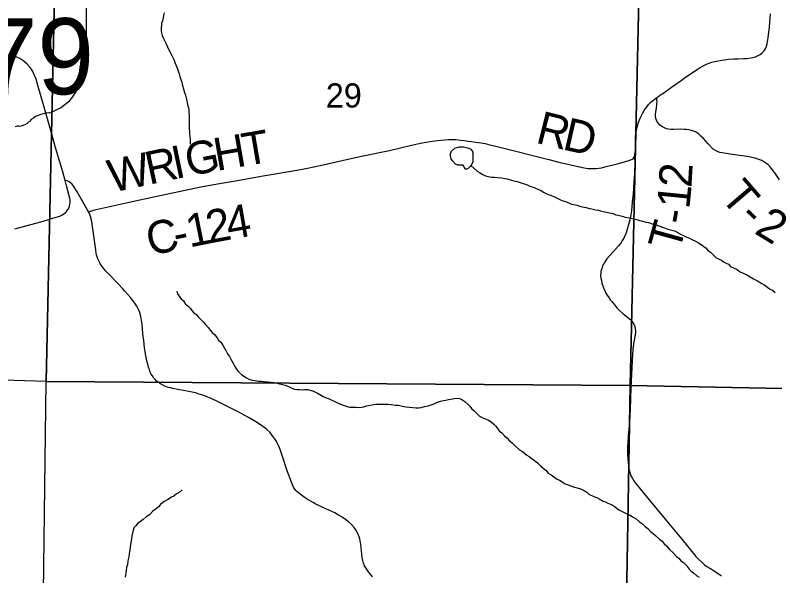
# Model space of a CAD drawing. Extents: x 0 to 34, y 0 to 22.
# Drawn here: x 27.832 to 29.148, y 18.224 to 19.195 of the extents above; entities that cross this region are included whole.
import ezdxf

# ---------------------------------------------------------------- set-up
doc = ezdxf.new("R2010")
doc.units = 0
for name, color, linetype in [('GM_X_Corporation', 7, 'Continuous'), ('GM_X_County_Road', 7, 'Continuous'), ('GM_X_County_Road_Text', 7, 'Continuous'), ('GM_X_Minor_River', 7, 'Continuous'), ('GM_X_Section_Text', 7, 'Continuous'), ('GM_X_State_Route', 7, 'Continuous'), ('GM_X_State_Shield', 7, 'Continuous'), ('GM_X_Township_Road', 7, 'Continuous'), ('GM_X_Township_Road_Text', 7, 'Continuous')]:
    doc.layers.add(name, color=color, linetype=linetype)

msp = doc.modelspace()

# ---------------------------------------------------------------- linework, layer by layer
at = {"layer": 'GM_X_Corporation'}
for points in [[(27.9077, 19.5783), (27.8861, 18.5601), (27.0567, 18.5863), (27.0782, 19.5962)], [(27.9077, 19.5783), (28.9198, 19.5578), (28.8973, 18.5532), (27.8861, 18.5601)], [(28.9198, 19.5578), (29.946, 19.5413), (29.9261, 18.5329), (28.8973, 18.5532)], [(28.8973, 18.5532), (28.8799, 17.5369), (27.873, 17.5549), (27.8861, 18.5601)], [(29.9261, 18.5329), (29.9011, 17.5188), (28.8799, 17.5369), (28.8973, 18.5532)]]:
    msp.add_lwpolyline(points, close=True, dxfattribs=at)
at = {"layer": 'GM_X_County_Road'}
for points in [[(27.9596, 18.8542), (27.9684, 18.8574), (27.9724, 18.8585), (28.0245, 18.8697), (28.0484, 18.875), (28.0779, 18.8812), (28.1351, 18.8938), (28.1541, 18.8976), (28.1862, 18.9034), (28.2137, 18.9082), (28.2618, 18.9166), (28.3063, 18.9241), (28.3235, 18.9271), (28.3384, 18.9301), (28.3494, 18.9324), (28.3603, 18.9348), (28.3858, 18.9406), (28.4292, 18.9501), (28.4807, 18.9609), (28.5185, 18.9696), (28.5342, 18.9732), (28.544, 18.9751), (28.5548, 18.9768), (28.56, 18.9774), (28.5698, 18.9786), (28.576, 18.9792), (28.5827, 18.9795), (28.5959, 18.9794), (28.6038, 18.9788), (28.6096, 18.9782), (28.6304, 18.9753), (28.6397, 18.9737), (28.6462, 18.9725), (28.6543, 18.9707), (28.6674, 18.9677), (28.6992, 18.9596), (28.7288, 18.9521), (28.7564, 18.9451), (28.7763, 18.9401), (28.7898, 18.9369), (28.8152, 18.931), (28.8211, 18.93), (28.825, 18.9295), (28.8282, 18.9293), (28.8312, 18.9292), (28.8387, 18.9294), (28.8434, 18.9299), (28.8476, 18.9307), (28.8561, 18.9327), (28.8732, 18.9369), (28.8814, 18.9391), (28.8957, 18.9434), (28.8997, 18.945), (28.9013, 18.9458), (28.9026, 18.9468), (28.9034, 18.9478), (28.9041, 18.949), (28.9047, 18.9504), (28.9053, 18.9523), (28.9058, 18.9544), (28.9062, 18.9573), (28.9065, 18.961), (28.9066, 18.9767), (28.907, 18.9847), (28.9074, 18.9889), (28.9084, 18.9956), (28.9095, 19.001), (28.9105, 19.0049), (28.9114, 19.008), (28.9137, 19.0137), (28.9161, 19.0189), (28.9196, 19.0256), (28.922, 19.0297), (28.9257, 19.0355), (28.9282, 19.0387), (28.9295, 19.0404), (28.9312, 19.0421), (28.933, 19.044), (28.9361, 19.0468), (28.9389, 19.0489), (28.9434, 19.0522), (28.9471, 19.0548), (28.9502, 19.0569), (28.9533, 19.0591), (28.9688, 19.0701), (28.9856, 19.082), (28.9936, 19.0877), (29.0138, 19.1012), (29.0186, 19.1043), (29.0228, 19.1067), (29.0286, 19.1096), (29.0325, 19.1114), (29.0388, 19.1136), (29.044, 19.115), (29.0561, 19.1172), (29.0611, 19.118), (29.0679, 19.1187), (29.0762, 19.1193), (29.0842, 19.1195), (29.0939, 19.1198), (29.1003, 19.1202), (29.1063, 19.121), (29.1104, 19.1219), (29.1148, 19.1232), (29.1193, 19.125), (29.1225, 19.1267), (29.1263, 19.1299), (29.129, 19.1328), (29.1308, 19.1353), (29.1322, 19.138), (29.1336, 19.1417), (29.1347, 19.1454), (29.1368, 19.1559), (29.1391, 19.1751), (29.1408, 19.1975)], [(27.9596, 18.8542), (27.9397, 18.8888), (27.9345, 18.8971), (27.9325, 18.9002), (27.9304, 18.9029), (27.9284, 18.9048), (27.9258, 18.9065), (27.9225, 18.9078), (27.9191, 18.9084)], [(28.4513, 18.222), (28.4445, 18.2303), (28.4418, 18.2339), (28.4396, 18.2372), (28.4376, 18.2407), (28.4357, 18.2454), (28.4342, 18.2503), (28.4332, 18.2553), (28.4322, 18.2668), (28.4317, 18.2727), (28.431, 18.2784), (28.4299, 18.2842), (28.429, 18.2877), (28.4276, 18.2927), (28.4266, 18.2954), (28.4255, 18.2978), (28.4234, 18.3017), (28.4222, 18.3035), (28.4195, 18.3073), (28.4146, 18.3128), (28.4095, 18.3171), (28.4043, 18.3212), (28.3984, 18.3252), (28.3926, 18.3289), (28.3857, 18.3326), (28.3706, 18.3399), (28.352, 18.3485), (28.3495, 18.3498), (28.347, 18.3512), (28.3397, 18.3554), (28.3328, 18.3599), (28.326, 18.3648), (28.3201, 18.3697), (28.3184, 18.3715), (28.3168, 18.3736), (28.3157, 18.3752), (28.3146, 18.3772), (28.3126, 18.3813), (28.3109, 18.3859), (28.3035, 18.4056), (28.2956, 18.4305), (28.2912, 18.4423), (28.2887, 18.4484), (28.286, 18.4541), (28.2837, 18.4581), (28.282, 18.4608), (28.2793, 18.4647), (28.2732, 18.4723), (28.2681, 18.4772), (28.2655, 18.4794), (28.2592, 18.4843), (28.2492, 18.4907), (28.2362, 18.4982), (28.2174, 18.5083), (28.2033, 18.5155), (28.1825, 18.5256), (28.1717, 18.5306), (28.1629, 18.5345), (28.1589, 18.536), (28.1512, 18.5386), (28.1446, 18.5406), (28.1361, 18.5427), (28.124, 18.545), (28.1048, 18.5484), (28.1013, 18.5491), (28.0973, 18.5501), (28.0942, 18.5512), (28.0915, 18.5523), (28.0883, 18.5539), (28.0838, 18.5564), (28.0806, 18.5585), (28.0766, 18.5616), (28.0746, 18.5635), (28.0723, 18.5662), (28.0699, 18.5699), (28.068, 18.5732), (28.0664, 18.5766), (28.0647, 18.5807), (28.0633, 18.5849), (28.0626, 18.5878), (28.0606, 18.5964), (28.0576, 18.6115), (28.0565, 18.6188), (28.0549, 18.6315), (28.0536, 18.643), (28.0521, 18.6594), (28.0513, 18.6663), (28.05, 18.6732), (28.0488, 18.6783), (28.0483, 18.6799), (28.046, 18.6852), (28.0431, 18.6907), (28.0398, 18.6959), (28.0362, 18.7009), (28.0322, 18.7057), (28.0218, 18.7176), (28.0186, 18.721), (28.011, 18.7292), (27.9922, 18.7487), (27.989, 18.7521), (27.9852, 18.7568), (27.9815, 18.7618), (27.9795, 18.765), (27.9772, 18.7693), (27.9757, 18.7727), (27.9744, 18.7761), (27.9733, 18.7798), (27.9727, 18.7826), (27.9718, 18.7882), (27.9663, 18.8292), (27.9648, 18.8374), (27.9625, 18.8465), (27.9608, 18.8515), (27.9596, 18.8542)]]:
    msp.add_lwpolyline(points, dxfattribs=at)
at = {"layer": 'GM_X_Minor_River'}
for points in [[(28.0902, 19.1991), (28.0895, 19.1945), (28.0885, 19.1903), (28.0874, 19.1853), (28.086, 19.1815), (28.0857, 19.1777), (28.085, 19.1728), (28.0854, 19.1682), (28.0859, 19.1644), (28.0867, 19.1599), (28.0891, 19.1546), (28.0914, 19.1501), (28.0938, 19.1452), (28.0962, 19.14), (28.0985, 19.1351), (28.1005, 19.1313), (28.1028, 19.1264), (28.1048, 19.1227), (28.1079, 19.117), (28.1091, 19.1133), (28.1135, 19.1019), (28.1163, 19.0933), (28.1175, 19.0887), (28.1191, 19.0838), (28.1207, 19.0793), (28.1215, 19.0755), (28.1247, 19.065), (28.1256, 19.0612), (28.1272, 19.0563), (28.1284, 19.0521), (28.13, 19.0438), (28.1308, 19.04), (28.1325, 19.0347), (28.1329, 19.0309), (28.133, 19.0264), (28.1334, 19.0215), (28.1339, 18.9979), (28.1343, 18.9942), (28.1344, 18.9896), (28.1349, 18.9847), (28.1353, 18.9805), (28.1355, 18.9718)], [(28.6234, 18.9368), (28.6205, 18.933), (28.6168, 18.9295), (28.613, 18.9275), (28.6103, 18.9313), (28.608, 18.935), (28.6034, 18.9353), (28.5989, 18.9353), (28.5951, 18.9371), (28.5904, 18.9423), (28.5877, 18.9464), (28.5865, 18.9506), (28.5864, 18.9555), (28.5882, 18.9597), (28.5938, 18.9644), (28.5976, 18.9656), (28.6013, 18.9668), (28.6089, 18.9669), (28.6135, 18.9659), (28.6173, 18.9648), (28.6218, 18.963), (28.6246, 18.9589), (28.625, 18.9547), (28.6252, 18.9456), (28.6249, 18.9407), (28.6234, 18.9368)], [(28.6217, 18.9346), (28.6327, 18.9249), (28.6366, 18.9226), (28.6423, 18.919), (28.6469, 18.9168), (28.6518, 18.9153), (28.6571, 18.9143), (28.6624, 18.9144), (28.6753, 18.9131), (28.6806, 18.912), (28.6844, 18.9114), (28.6917, 18.9092), (28.6958, 18.9081), (28.7019, 18.9067), (28.7072, 18.9049), (28.7122, 18.9035), (28.7179, 18.9017), (28.724, 18.8988), (28.7312, 18.8963), (28.7385, 18.893), (28.7431, 18.8912), (28.7476, 18.8886), (28.7557, 18.8845), (28.7602, 18.8831), (28.7675, 18.8798), (28.7743, 18.8765), (28.7793, 18.874), (28.7854, 18.8722), (28.7923, 18.8696), (28.7961, 18.8678), (28.7999, 18.8671), (28.8059, 18.8657), (28.8101, 18.8643), (28.8143, 18.8632), (28.8215, 18.8618), (28.8265, 18.86), (28.831, 18.8593), (28.8382, 18.8579), (28.8424, 18.8573), (28.8462, 18.8562), (28.8508, 18.8548), (28.8595, 18.8534), (28.8679, 18.8513), (28.8725, 18.8491), (28.8766, 18.8484), (28.8838, 18.847), (28.8888, 18.8452), (28.8964, 18.8438), (28.9036, 18.842), (28.9093, 18.841), (28.9135, 18.8396), (28.9173, 18.8389), (28.9245, 18.8367), (28.9291, 18.8357), (28.9355, 18.8335), (28.9412, 18.8321), (28.945, 18.8306), (28.9489, 18.8296), (28.9534, 18.8277), (28.9572, 18.8267), (28.9629, 18.8245), (28.9694, 18.8223), (28.974, 18.8213), (28.9801, 18.8187), (28.9847, 18.8158), (28.9896, 18.8136), (28.9957, 18.8103), (29.0003, 18.8085), (29.0041, 18.8066), (29.0106, 18.8037), (29.0156, 18.8004), (29.0205, 18.7978), (29.0252, 18.7941), (29.0294, 18.7912), (29.0321, 18.7874), (29.0367, 18.7845), (29.0401, 18.7807), (29.0463, 18.7744), (29.0555, 18.7704), (29.0593, 18.7678), (29.0639, 18.7652), (29.0677, 18.7634), (29.0715, 18.7597), (29.083, 18.7542), (29.0868, 18.7512), (29.0998, 18.745), (29.1113, 18.738), (29.1181, 18.7347), (29.1254, 18.7299), (29.1296, 18.7277), (29.1335, 18.7251), (29.1388, 18.721), (29.1442, 18.7185), (29.1484, 18.7148)], [(28.1123, 18.7168), (28.1136, 18.7123), (28.1159, 18.7085), (28.1198, 18.7036), (28.1236, 18.6999), (28.1275, 18.6943), (28.1313, 18.6917), (28.1352, 18.6876), (28.1383, 18.6835), (28.1418, 18.6794), (28.146, 18.6764), (28.1498, 18.6719), (28.1533, 18.6682), (28.1579, 18.6637), (28.1618, 18.6592), (28.1668, 18.654), (28.1699, 18.6495), (28.1734, 18.645), (28.178, 18.6409), (28.1819, 18.6361), (28.1846, 18.6319), (28.1884, 18.6282), (28.1923, 18.6222), (28.197, 18.6143), (28.2001, 18.6083), (28.2036, 18.6035), (28.2056, 18.5993), (28.2079, 18.5952), (28.2107, 18.5907), (28.2126, 18.5865), (28.2158, 18.5817), (28.2192, 18.5768), (28.2246, 18.5723), (28.2284, 18.5698), (28.2327, 18.5668), (28.2372, 18.5646), (28.2426, 18.5628), (28.2479, 18.5618), (28.2536, 18.5611), (28.2585, 18.5608), (28.2627, 18.5605), (28.2702, 18.5599), (28.2809, 18.5585), (28.2862, 18.5575), (28.29, 18.5561), (28.2953, 18.555), (28.3002, 18.554), (28.3044, 18.5521), (28.3117, 18.5489), (28.3159, 18.547), (28.3212, 18.5464), (28.325, 18.5464), (28.3295, 18.5461), (28.334, 18.5466), (28.339, 18.5463), (28.3435, 18.5452), (28.3488, 18.5438), (28.3534, 18.5412), (28.3572, 18.5398), (28.366, 18.5343), (28.3699, 18.5324), (28.3763, 18.5303), (28.3809, 18.5277), (28.3859, 18.5259), (28.3908, 18.5233), (28.3946, 18.5219), (28.3988, 18.5197), (28.4072, 18.5168), (28.4121, 18.5161), (28.4159, 18.5158), (28.4228, 18.5156), (28.4269, 18.5152), (28.4322, 18.5157), (28.4364, 18.5166), (28.4416, 18.5182), (28.4477, 18.5194), (28.4529, 18.5203), (28.4567, 18.5211), (28.4692, 18.5213), (28.473, 18.521), (28.4775, 18.5211), (28.4836, 18.5204), (28.4874, 18.5201), (28.4912, 18.5194), (28.4961, 18.5191), (28.5007, 18.5181), (28.5052, 18.517), (28.5094, 18.5163), (28.5155, 18.5157), (28.5208, 18.515), (28.5268, 18.5147), (28.5317, 18.5148), (28.5355, 18.5153), (28.5412, 18.5169), (28.5479, 18.5182), (28.5581, 18.5218), (28.5622, 18.5237), (28.569, 18.5261), (28.5739, 18.5273), (28.578, 18.5282), (28.5826, 18.529)], [(28.5826, 18.529), (28.5867, 18.5299), (28.5924, 18.5311), (28.5973, 18.5316), (28.6018, 18.5309), (28.606, 18.5291), (28.611, 18.5257), (28.6164, 18.5213), (28.6199, 18.5175), (28.6229, 18.5138), (28.6272, 18.5097), (28.6314, 18.5052), (28.6364, 18.5004), (28.6425, 18.4975), (28.6479, 18.4949), (28.6521, 18.4935), (28.6567, 18.4905), (28.6613, 18.4864), (28.6651, 18.4827), (28.6678, 18.4789), (28.6709, 18.4745), (28.6755, 18.4711), (28.6798, 18.4659), (28.6844, 18.4622), (28.6886, 18.4577), (28.6929, 18.454), (28.699, 18.448), (28.7059, 18.4417), (28.7113, 18.4388), (28.7186, 18.4324), (28.7224, 18.4302), (28.7278, 18.4262), (28.7324, 18.4228), (28.737, 18.4191), (28.742, 18.4139), (28.747, 18.4102), (28.7512, 18.4068), (28.7555, 18.4012), (28.7608, 18.3983), (28.765, 18.395), (28.7712, 18.3913), (28.775, 18.3894), (28.7796, 18.3865), (28.7849, 18.3832), (28.7891, 18.3817), (28.7929, 18.3799), (28.8009, 18.377), (28.81, 18.3749), (28.8142, 18.3731), (28.818, 18.3712), (28.8223, 18.3683), (28.8261, 18.3649), (28.8356, 18.3602), (28.8398, 18.3591), (28.8436, 18.3569), (28.8505, 18.3532), (28.8547, 18.3518), (28.8589, 18.3496), (28.8646, 18.347), (28.87, 18.3445), (28.878, 18.3378), (28.8834, 18.3352), (28.8903, 18.3316), (28.8963, 18.329), (28.9025, 18.325), (28.9078, 18.3224), (28.9136, 18.3172), (28.9189, 18.3135), (28.9236, 18.309), (28.9282, 18.3053), (28.9328, 18.3005), (28.9374, 18.2968), (28.942, 18.2927), (28.9489, 18.2867), (28.9528, 18.2838), (28.9566, 18.2789), (28.9612, 18.2748), (28.9663, 18.2688), (28.972, 18.2636), (28.9778, 18.2569), (28.9824, 18.2536), (28.9855, 18.2498), (28.9901, 18.2469), (28.9944, 18.242), (28.9994, 18.2349), (29.0032, 18.2316), (29.0071, 18.2286), (29.0132, 18.2238), (29.017, 18.2212)], [(28.1214, 18.3725), (28.1162, 18.3678), (28.1117, 18.3655), (28.1069, 18.3616), (28.1031, 18.36), (28.0967, 18.3561), (28.0904, 18.3526), (28.084, 18.3472), (28.0807, 18.3433), (28.0747, 18.3383), (28.071, 18.3359), (28.065, 18.3294), (28.0594, 18.3259), (28.0538, 18.3212), (28.0486, 18.317), (28.0441, 18.3142), (28.0415, 18.31), (28.0378, 18.3065), (28.0368, 18.3027), (28.0343, 18.2928), (28.0336, 18.2879), (28.0326, 18.2814), (28.0323, 18.2772), (28.0316, 18.273), (28.0309, 18.2681), (28.0295, 18.2624), (28.0289, 18.2563), (28.0275, 18.2495), (28.0268, 18.2426), (28.0254, 18.2388), (28.0247, 18.2327), (28.0227, 18.2213)]]:
    msp.add_lwpolyline(points, dxfattribs=at)
at = {"layer": 'GM_X_State_Route'}
msp.add_lwpolyline([(27.8318, 18.8247), (27.8767, 18.8371), (27.9073, 18.8462), (27.9099, 18.8471), (27.9132, 18.8487), (27.9156, 18.8501), (27.9198, 18.8534), (27.9238, 18.8582), (27.9247, 18.8597), (27.9259, 18.8623), (27.9264, 18.8641), (27.9271, 18.8668), (27.9275, 18.8713), (27.9274, 18.8743), (27.9268, 18.8778), (27.9212, 18.8992), (27.9191, 18.9084), (27.9146, 18.9239), (27.9074, 18.9485), (27.9018, 18.9674), (27.8952, 18.9912), (27.8848, 19.0277), (27.8711, 19.0753), (27.8684, 19.0843), (27.866, 19.0908), (27.8629, 19.0973), (27.8609, 19.1006), (27.8583, 19.1043), (27.8531, 19.1105), (27.8487, 19.1143), (27.8455, 19.1167), (27.8404, 19.1199), (27.8351, 19.1224), (27.8291, 19.1244)], dxfattribs=at)
at = {"layer": 'GM_X_State_Shield'}
for p, q in [((27.9559, 19.1477), (27.9559, 19.2524)), ((27.9558, 19.1477), (27.9559, 19.1477))]:
    msp.add_line(p, q, dxfattribs=at)
for centre, major_axis, start_param, end_param in [((27.955, 19.14), (0.00568, 0), 1.883978, 3.671073), ((27.9519, 19.1473), (0.00393, 0), 5.05454, 6.418171), ((27.9189, 19.1268), (0.0341, 0), 5.934695, 6.695948), ((27.969, 19.1039), (0.0248, 0), 2.387724, 3.262537), ((27.858, 19.0906), (0.0874, 0), 5.101752, 6.440018), ((27.8949, 18.9877), (0.0479, 0), 1.647645, 2.488434), ((27.8374, 18.997), (0.00752, 0), 1.147584, 2.315152), ((27.8342, 19.0245), (0.0282, 0), 4.937069, 5.64225)]:
    msp.add_ellipse(centre, major_axis=major_axis, ratio=0.8, start_param=start_param, end_param=end_param, dxfattribs=at)
at = {"layer": 'GM_X_Township_Road'}
for points in [[(29.1562, 18.9098), (29.1479, 18.9218), (29.1453, 18.9256), (29.1424, 18.9295), (29.1394, 18.9329), (29.1358, 18.9362), (29.1324, 18.9387), (29.1291, 18.941), (29.1256, 18.943), (29.1202, 18.9452), (29.114, 18.9471), (29.1085, 18.9485), (29.1003, 18.9501), (29.087, 18.9519), (29.0706, 18.9545), (29.0568, 18.9563), (29.0529, 18.9572), (29.0501, 18.9581), (29.0475, 18.9592), (29.0453, 18.9604), (29.0413, 18.9632), (29.0327, 18.9722), (29.0243, 18.9813), (29.02, 18.9857), (29.0172, 18.9883), (29.0139, 18.9906), (29.0107, 18.9927), (29.0072, 18.9943), (29.0038, 18.9954), (28.9993, 18.9963), (28.9952, 18.9969), (28.991, 18.9972), (28.9848, 18.9973), (28.9727, 18.997), (28.9681, 18.9971), (28.9638, 18.9975), (28.9606, 18.9983), (28.9568, 18.9998), (28.9535, 19.0014), (28.9489, 19.0045), (28.9452, 19.0091), (28.9439, 19.0115), (28.9431, 19.0133), (28.9422, 19.0163), (28.9416, 19.0201), (28.9415, 19.0234), (28.9417, 19.0268), (28.9429, 19.0348), (28.9437, 19.0401), (28.9439, 19.0419), (28.944, 19.0444), (28.9438, 19.0496), (28.9434, 19.0522)], [(28.9034, 18.9478), (28.9048, 18.9444), (28.9053, 18.9424), (28.9054, 18.9397), (28.9048, 18.9207), (28.904, 18.9061), (28.9027, 18.8854), (28.9012, 18.8708), (28.9005, 18.8635), (28.8998, 18.8561), (28.8987, 18.8491), (28.8973, 18.8425), (28.8958, 18.8367), (28.8906, 18.8182), (28.8891, 18.8141), (28.8872, 18.81), (28.8845, 18.8051), (28.8811, 18.8), (28.8774, 18.7955), (28.8686, 18.7855), (28.8619, 18.7783), (28.8572, 18.7727), (28.8534, 18.7674), (28.8523, 18.7656), (28.851, 18.763), (28.849, 18.7587), (28.8482, 18.7564), (28.8474, 18.7533), (28.8468, 18.7501), (28.8465, 18.7479), (28.8464, 18.7427), (28.8468, 18.7396), (28.8476, 18.7351), (28.8487, 18.7306), (28.8507, 18.7245), (28.8521, 18.721), (28.8524, 18.7201), (28.8556, 18.7136), (28.8588, 18.7083), (28.8609, 18.7052), (28.8637, 18.7015), (28.8656, 18.6992)], [(28.8656, 18.6992), (28.871, 18.6924), (28.8746, 18.6882), (28.8797, 18.6828), (28.8847, 18.6782), (28.8876, 18.6758), (28.8987, 18.6669), (28.9017, 18.6631), (28.9037, 18.6597), (28.905, 18.6566), (28.9059, 18.6534), (28.9063, 18.6515), (28.9066, 18.6476), (28.9065, 18.6448), (28.9032, 18.6258), (28.9022, 18.6159), (28.9014, 18.6072), (28.8986, 18.5502), (28.8973, 18.5121), (28.8962, 18.4902), (28.8956, 18.4827), (28.8939, 18.4659), (28.8932, 18.4548), (28.8929, 18.4472), (28.8928, 18.4408), (28.8929, 18.4345), (28.8935, 18.426), (28.8946, 18.4147), (28.8954, 18.4085), (28.8961, 18.4048), (28.8973, 18.4008), (28.8989, 18.3967), (28.9013, 18.3921), (28.9038, 18.388)], [(28.9038, 18.388), (28.9071, 18.3836), (28.9223, 18.3653), (28.9555, 18.325), (28.987, 18.2872), (29.0045, 18.2659), (29.009, 18.26), (29.0114, 18.2572), (29.0162, 18.252), (29.0223, 18.2464), (29.0265, 18.2429), (29.0305, 18.2399), (29.0352, 18.2368), (29.0428, 18.2321), (29.0537, 18.2249), (29.0557, 18.2234)]]:
    msp.add_lwpolyline(points, dxfattribs=at)

# ---------------------------------------------------------------- texts
at = {"layer": 'GM_X_County_Road_Text'}
for s, rotation, p in [('R', 345.9212, (28.7319, 18.9745)), ('D', 347.1534, (28.7784, 18.9629)), ('H', 9.8067, (28.1812, 18.925)), ('T', 9.7195, (28.2304, 18.9335)), ('G', 10.7734, (28.1323, 18.9157)), ('R', 12.1351, (28.0642, 18.9012)), ('I', 11.7769, (28.1097, 18.9109)), ('W', 12.1591, (27.9998, 18.8873)), ('4', 9.9371, (28.2025, 18.8058)), ('2', 10.7629, (28.1683, 18.7993)), ('C', 11.959, (28.0658, 18.778)), ('1', 11.3936, (28.1342, 18.7924)), ('-', 11.7998, (28.1115, 18.7877))]:
    msp.add_text(s, height=0.0568, rotation=rotation, dxfattribs=at).set_placement(p)
at = {"layer": 'GM_X_Section_Text'}
msp.add_text('29', height=0.04186, rotation=0, dxfattribs=at).set_placement((28.3704, 19.0351))
at = {"layer": 'GM_X_State_Shield'}
msp.add_text('379', height=0.13184, dxfattribs=at).set_placement((27.6747, 19.058))
at = {"layer": 'GM_X_Township_Road_Text'}
for s, rotation, p in [('2', 86.6886, (29.0035, 18.8954)), ('T', 310.6654, (29.0519, 18.8791)), ('1', 84.3061, (28.9999, 18.858)), ('-', 79.9383, (28.9952, 18.8303)), ('-', 315.4085, (29.0831, 18.8431)), ('2', 328.4307, (29.1107, 18.8181)), ('T', 74.5709, (28.9826, 18.7837))]:
    msp.add_text(s, height=0.0568, rotation=rotation, dxfattribs=at).set_placement(p)

doc.saveas('drawing.dxf')
